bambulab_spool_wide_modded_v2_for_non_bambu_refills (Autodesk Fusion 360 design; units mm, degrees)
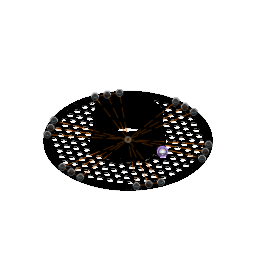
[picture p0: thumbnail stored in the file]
parameter "lattice_diameter" = 10.25
parameter "lattice_thickness" = 3.75
parameter "hole_diameter" = 3.5 comment "Hole Diameter of the rim"
base_mesh_feature "Base Mesh Feature"
convert_mesh "Convert Mesh" bodies "bambulab_spool_wide"
sketch "Sketch13" plane through (0, 0, -16.75) normal (0, 0, 1) x axis (-1, 0, 0)
  line L1 (92.6217, -5.7502) -> (99.4206, -5.9753)
  line L2 (92.483, -7.6633) -> (92.6217, -5.7502)
  line L3 (99.4206, -5.9753) -> (92.483, -7.6633)
  line L4 (0, 0) -> (-74.6153, -60.4003)
  line L5 (-89.6135, -34.4171) -> (0, 0)
  line L6 (-74.6153, -60.4003) -> (-89.6135, -34.4171)
  line L7 (-15.0006, -94.8162) -> (0, 0)
  line L8 (15.0006, -94.8189) -> (-15.0006, -94.8162)
  line L9 (0, 0) -> (15.0006, -94.8189)
  line L10 (0, 0) -> (74.6129, -60.399)
  line L11 (0, 0) -> (89.6159, -34.4185)
  line L12 (74.6129, -60.399) -> (89.6159, -34.4185)
  line L13 (89.6135, 34.4171) -> (0, 0)
  line L14 (74.6153, 60.4003) -> (89.6135, 34.4171)
  line L15 (0, 0) -> (74.6153, 60.4003)
  line L16 (0, 0) -> (-15.0006, 94.8189)
  line L17 (15.0006, 94.8162) -> (-15.0006, 94.8189)
  line L18 (0, 0) -> (15.0006, 94.8162)
  line L19 (0, 0) -> (-89.6159, 34.4185)
  line L20 (-89.6159, 34.4185) -> (-74.6129, 60.399)
  line L21 (0, 0) -> (-74.6129, 60.399)
  line L22 (0, 0) -> (-82.1144, 47.4088)
  line L23 (0, 0) -> (0, 94.8175)
  line L24 (0, 0) -> (82.1144, 47.4087)
  line L25 (0, 0) -> (82.1144, -47.4088)
  line L26 (0, 0) -> (0, -94.8175)
  line L27 (0, 0) -> (-82.1144, -47.4087)
  circle C1 centre (15.0006, -94.8189) radius 2
  circle C2 centre (-15.0006, -94.8162) radius 2
  circle C3 centre (89.6159, -34.4185) radius 2
  circle C4 centre (74.6153, 60.4003) radius 2
  circle C5 centre (-15.0006, 94.8189) radius 2
  circle C6 centre (-89.6159, 34.4185) radius 2
  circle C7 centre (-74.6153, -60.4003) radius 2
  circle C8 centre (74.6129, -60.399) radius 2
  circle C9 centre (89.6135, 34.4171) radius 2
  circle C10 centre (15.0006, 94.8162) radius 2
  circle C11 centre (-74.6129, 60.399) radius 2
  circle C12 centre (-89.6135, -34.4171) radius 2
  point P1 (0, 0)
  point P7 (0, 0)
  point P12 (-74.6153, -60.4003)
  point P18 (-74.6153, -60.4003)
  point P19 (0, 0)
  point P17 (-89.6135, -34.4171)
  point P20 (-89.6135, -34.4171)
  point P21 (-74.6153, -60.4003)
  point P22 (-82.1144, -47.4087)
  point P23 (0, 0)
  point P6 (-15.0006, -94.8162)
  point P24 (-15.0006, -94.8162)
  point P5 (15.0006, -94.8189)
  point P25 (15.0006, -94.8189)
  point P26 (0, 0)
  point P13 (74.6129, -60.399)
  point P27 (74.6129, -60.399)
  point P28 (0, 0)
  point P8 (89.6159, -34.4185)
  point P29 (89.6159, -34.4185)
  point P30 (0, 0)
  point P31 (89.6159, -34.4185)
  point P14 (89.6135, 34.4171)
  point P32 (89.6135, 34.4171)
  point P9 (74.6153, 60.4003)
  point P33 (74.6153, 60.4003)
  point P34 (0, 0)
  point P10 (-15.0006, 94.8189)
  point P35 (-15.0006, 94.8189)
  point P36 (0, 0)
  point P37 (-15.0006, 94.8189)
  point P15 (15.0006, 94.8162)
  point P38 (15.0006, 94.8162)
  point P39 (15.0006, 94.8162)
  point P40 (0, 0)
  point P11 (-89.6159, 34.4185)
  point P41 (-89.6159, 34.4185)
  point P42 (0, 0)
  point P16 (-74.6129, 60.399)
  point P43 (-74.6129, 60.399)
  point P44 (-89.6159, 34.4185)
  point P45 (0, -94.8175)
  point P46 (82.1144, -47.4088)
  point P47 (82.1144, 47.4087)
  point P48 (0, 94.8175)
  point P49 (-82.1144, 47.4088)
  point P50 (-82.1144, 47.4088)
  point P51 (0, 0)
  point P52 (0, 94.8175)
  point P53 (0, 0)
  point P54 (82.1144, 47.4087)
  point P55 (82.1144, -47.4088)
  point P56 (0, -94.8175)
  point P57 (-82.1144, -47.4087)
  point P58 (0, 0)
  coincident P1 P7
  coincident P12 P18
  coincident P7 P19
  coincident P17 P20
  coincident P12 P21
  midpoint L6 P22
  coincident P7 P23
  coincident P6 P24
  coincident P5 P25
  coincident P1 P26
  coincident P13 P27
  coincident P1 P28
  coincident P8 P29
  coincident P7 P30
  coincident P8 P31
  coincident P14 P32
  coincident P9 P33
  coincident P1 P34
  coincident P10 P35
  coincident P1 P36
  coincident P10 P37
  coincident P15 P38
  coincident P15 P39
  coincident P1 P40
  coincident P11 P41
  coincident P7 P42
  coincident P16 P43
  coincident P11 P44
  midpoint L8 P45
  midpoint L12 P46
  midpoint L14 P47
  midpoint L17 P48
  midpoint L20 P49
  coincident P49 P50
  coincident P1 P51
  coincident P48 P52
  coincident P7 P53
  coincident P47 P54
  coincident P46 P55
  coincident P45 P56
  coincident P22 P57
  coincident P1 P58
  dimension "d48" diameter C1 = 4
  dimension "d49" diameter C2 = 4
  dimension "d51" C-Pattern1-Angle = 360
  dimension "d53" C-Pattern2-Angle = 360
extrude "Extrude5" cut sketch "Sketch13" profile of C3 C4 C6 C7 C8 C9 C11 C12 against normal blind 25
sketch "Sketch14" plane through (0, 0, -17.85) normal (0, 0, 1) x axis (-1, 0, 0)
  line L1 (-23.297, 37.7968) -> (-24.4167, 37.0834)
  line L2 (-2.5625, 4.4384) -> (2.5625, 4.4384)
  line L3 (-5.125, 0) -> (-2.5625, 4.4384)
  line L4 (-2.5625, -4.4384) -> (-5.125, 0)
  line L5 (2.5625, -4.4384) -> (-2.5625, -4.4384)
  line L6 (5.125, 0) -> (2.5625, -4.4384)
  line L7 (2.5625, 4.4384) -> (5.125, 0)
  line L8 (5.125, -12.6268) -> (2.5625, -17.0651)
  line L9 (2.5625, -8.1884) -> (5.125, -12.6268)
  line L10 (-2.5625, -8.1884) -> (2.5625, -8.1884)
  line L11 (-5.125, -12.6268) -> (-2.5625, -8.1884)
  line L12 (-2.5625, -17.0651) -> (-5.125, -12.6268)
  line L13 (2.5625, -17.0651) -> (-2.5625, -17.0651)
  line L14 (0, -45.5) -> (0, 45.5)
  line L15 (-37, 0) -> (37, 0)
  line L16 (16.0601, -6.3134) -> (13.4976, -10.7518)
  line L17 (13.4976, -1.875) -> (16.0601, -6.3134)
  line L18 (8.3726, -1.875) -> (13.4976, -1.875)
  line L19 (5.8101, -6.3134) -> (8.3726, -1.875)
  line L20 (8.3726, -10.7518) -> (5.8101, -6.3134)
  line L21 (13.4976, -10.7518) -> (8.3726, -10.7518)
  line L22 (13.4976, 10.7518) -> (16.0601, 6.3134)
  line L23 (8.3726, 10.7518) -> (13.4976, 10.7518)
  line L24 (5.8101, 6.3134) -> (8.3726, 10.7518)
  line L25 (8.3726, 1.875) -> (5.8101, 6.3134)
  line L26 (13.4976, 1.875) -> (8.3726, 1.875)
  line L27 (16.0601, 6.3134) -> (13.4976, 1.875)
  line L28 (-5.125, -17.0651) -> (-5.125, 10.7518)
  line L29 (16.0601, -17.0651) -> (16.0601, 10.7518)
  line L30 (-5.125, 10.7518) -> (16.0601, 10.7518)
  line L31 (-5.125, -17.0651) -> (16.0601, -17.0651)
  line L32 (-92.4279, -85.5158) -> (-89.8654, -89.9542)
  line L33 (-89.8654, -89.9542) -> (-92.4279, -94.3926)
  line L34 (-92.4279, -94.3926) -> (-97.5529, -94.3926)
  line L35 (-97.5529, -94.3926) -> (-100.1154, -89.9542)
  line L36 (-100.1154, -89.9542) -> (-97.5529, -85.5158)
  line L37 (-97.5529, -85.5158) -> (-92.4279, -85.5158)
  line L38 (-92.4279, -98.1426) -> (-89.8654, -102.581)
  line L39 (-97.5529, -98.1426) -> (-92.4279, -98.1426)
  line L40 (-100.1154, -102.581) -> (-97.5529, -98.1426)
  line L41 (-97.5529, -107.0194) -> (-100.1154, -102.581)
  line L42 (-92.4279, -107.0194) -> (-97.5529, -107.0194)
  line L43 (-89.8654, -102.581) -> (-92.4279, -107.0194)
  line L44 (-100.8005, -96.2676) -> (-103.363, -100.706)
  line L45 (-103.363, -91.8292) -> (-100.8005, -96.2676)
  line L46 (-108.488, -91.8292) -> (-103.363, -91.8292)
  line L47 (-111.0505, -96.2676) -> (-108.488, -91.8292)
  line L48 (-108.488, -100.706) -> (-111.0505, -96.2676)
  line L49 (-103.363, -100.706) -> (-108.488, -100.706)
  line L50 (-108.488, -104.456) -> (-103.363, -104.456)
  line L51 (-103.363, -104.456) -> (-100.8005, -108.8944)
  line L52 (-100.8005, -108.8944) -> (-103.363, -113.3327)
  line L53 (-103.363, -113.3327) -> (-108.488, -113.3327)
  line L54 (-108.488, -113.3327) -> (-111.0505, -108.8944)
  line L55 (-111.0505, -108.8944) -> (-108.488, -104.456)
  line L56 (-71.2428, -85.5158) -> (-68.6803, -89.9542)
  line L57 (-68.6803, -89.9542) -> (-71.2428, -94.3926)
  line L58 (-71.2428, -94.3926) -> (-76.3678, -94.3926)
  line L59 (-76.3678, -94.3926) -> (-78.9303, -89.9542)
  line L60 (-78.9303, -89.9542) -> (-76.3678, -85.5158)
  line L61 (-76.3678, -85.5158) -> (-71.2428, -85.5158)
  line L62 (-71.2428, -98.1426) -> (-68.6803, -102.581)
  line L63 (-76.3678, -98.1426) -> (-71.2428, -98.1426)
  line L64 (-78.9303, -102.581) -> (-76.3678, -98.1426)
  line L65 (-76.3678, -107.0194) -> (-78.9303, -102.581)
  line L66 (-71.2428, -107.0194) -> (-76.3678, -107.0194)
  line L67 (-68.6803, -102.581) -> (-71.2428, -107.0194)
  line L68 (-79.6154, -96.2676) -> (-82.1779, -100.706)
  line L69 (-82.1779, -91.8292) -> (-79.6154, -96.2676)
  line L70 (-87.3029, -91.8292) -> (-82.1779, -91.8292)
  line L71 (-89.8654, -96.2676) -> (-87.3029, -91.8292)
  line L72 (-87.3029, -100.706) -> (-89.8654, -96.2676)
  line L73 (-82.1779, -100.706) -> (-87.3029, -100.706)
  line L74 (-87.3029, -104.456) -> (-82.1779, -104.456)
  line L75 (-82.1779, -104.456) -> (-79.6154, -108.8944)
  line L76 (-79.6154, -108.8944) -> (-82.1779, -113.3327)
  line L77 (-82.1779, -113.3327) -> (-87.3029, -113.3327)
  line L78 (-87.3029, -113.3327) -> (-89.8654, -108.8944)
  line L79 (-89.8654, -108.8944) -> (-87.3029, -104.456)
  line L80 (-50.0577, -85.5158) -> (-47.4952, -89.9542)
  line L81 (-47.4952, -89.9542) -> (-50.0577, -94.3926)
  line L82 (-50.0577, -94.3926) -> (-55.1827, -94.3926)
  line L83 (-55.1827, -94.3926) -> (-57.7452, -89.9542)
  line L84 (-57.7452, -89.9542) -> (-55.1827, -85.5158)
  line L85 (-55.1827, -85.5158) -> (-50.0577, -85.5158)
  line L86 (-50.0577, -98.1426) -> (-47.4952, -102.581)
  line L87 (-55.1827, -98.1426) -> (-50.0577, -98.1426)
  line L88 (-57.7452, -102.581) -> (-55.1827, -98.1426)
  line L89 (-55.1827, -107.0194) -> (-57.7452, -102.581)
  line L90 (-50.0577, -107.0194) -> (-55.1827, -107.0194)
  line L91 (-47.4952, -102.581) -> (-50.0577, -107.0194)
  line L92 (-58.4303, -96.2676) -> (-60.9928, -100.706)
  line L93 (-60.9928, -91.8292) -> (-58.4303, -96.2676)
  line L94 (-66.1178, -91.8292) -> (-60.9928, -91.8292)
  line L95 (-68.6803, -96.2676) -> (-66.1178, -91.8292)
  line L96 (-66.1178, -100.706) -> (-68.6803, -96.2676)
  line L97 (-60.9928, -100.706) -> (-66.1178, -100.706)
  line L98 (-66.1178, -104.456) -> (-60.9928, -104.456)
  line L99 (-60.9928, -104.456) -> (-58.4303, -108.8944)
  line L100 (-58.4303, -108.8944) -> (-60.9928, -113.3327)
  line L101 (-60.9928, -113.3327) -> (-66.1178, -113.3327)
  line L102 (-66.1178, -113.3327) -> (-68.6803, -108.8944)
  line L103 (-68.6803, -108.8944) -> (-66.1178, -104.456)
  line L104 (-28.8726, -85.5158) -> (-26.3101, -89.9542)
  line L105 (-26.3101, -89.9542) -> (-28.8726, -94.3926)
  line L106 (-28.8726, -94.3926) -> (-33.9976, -94.3926)
  line L107 (-33.9976, -94.3926) -> (-36.5601, -89.9542)
  line L108 (-36.5601, -89.9542) -> (-33.9976, -85.5158)
  line L109 (-33.9976, -85.5158) -> (-28.8726, -85.5158)
  line L110 (-28.8726, -98.1426) -> (-26.3101, -102.581)
  line L111 (-33.9976, -98.1426) -> (-28.8726, -98.1426)
  line L112 (-36.5601, -102.581) -> (-33.9976, -98.1426)
  line L113 (-33.9976, -107.0194) -> (-36.5601, -102.581)
  line L114 (-28.8726, -107.0194) -> (-33.9976, -107.0194)
  line L115 (-26.3101, -102.581) -> (-28.8726, -107.0194)
  line L116 (-37.2452, -96.2676) -> (-39.8077, -100.706)
  line L117 (-39.8077, -91.8292) -> (-37.2452, -96.2676)
  line L118 (-44.9327, -91.8292) -> (-39.8077, -91.8292)
  line L119 (-47.4952, -96.2676) -> (-44.9327, -91.8292)
  line L120 (-44.9327, -100.706) -> (-47.4952, -96.2676)
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  point P1 (0, 0)
  point P4 (0, 0)
  point P5 (0, 0)
  point P6 (0, 0)
  point P13 (0, 0)
  point P20 (0, -12.6268)
  point P9 (-5.125, 0)
  point P26 (16.0601, -6.3134)
  point P41 (16.0601, -17.0651)
  point P42 (-5.125, -17.0651)
  point P39 (-5.125, 10.7518)
  point P40 (16.0601, 10.7518)
  point P12 (5.125, 0)
  point P7 (2.5625, 4.4384)
  point P10 (-2.5625, -4.4384)
  point P15 (5.125, -12.6268)
  point P18 (-5.125, -12.6268)
  point P14 (2.5625, -17.0651)
  point P17 (-2.5625, -8.1884)
  point P29 (5.8101, -6.3134)
  point P32 (16.0601, 6.3134)
  point P35 (5.8101, 6.3134)
  coincident P1 P4
  coincident P1 P5
  coincident P1 P6
  coincident P5 P13
  vertical L14
  horizontal L15
  coincident P1 L14
  midpoint P4 L15
  midpoint P1 L14
  coincident P20 L14
  parallel L5 L15
  parallel L15 L21
  parallel L15 L26
  vertical L28
  vertical L29
  coincident P9 L28
  coincident P26 L29
  perpendicular L29 L30
  horizontal L31
  collinear L23 L30
  collinear L13 L31
  coincident L29 P41
  coincident L28 P42
  coincident P39 L30
  coincident L29 P40
  dimension "d56" diameter = 183.4
  dimension "d57" diameter = 89
  dimension "d62" diameter = 179.65 (= "183.4 mm - lattice_thickness")
  dimension "d63" distance P9 P12 = 10.25 (= "lattice_diameter")
  dimension "d64" distance P7 P10 = 10.25 (= "lattice_diameter")
  dimension "d65" distance P15 P18 = 10.25 (= "lattice_diameter")
  dimension "d66" distance P14 P17 = 10.25 (= "lattice_diameter")
  dimension "d67" distance L5 L10 = 3.75 (= "lattice_thickness")
  dimension "d68" distance P26 P29 = 10.25 (= "lattice_diameter")
  dimension "d69" distance L6 L19 = 3.75 (= "lattice_thickness")
  dimension "d70" distance L9 L20 = 3.75 (= "lattice_thickness")
  dimension "d71" distance P32 P35 = 10.25 (= "lattice_diameter")
  dimension "d72" distance L18 L26 = 3.75 (= "lattice_thickness")
  dimension "d73" distance L7 L25 = 3.75 (= "lattice_thickness")
  dimension "d74" distance P41 P42 = 21.1851
  dimension "d75" distance P40 P41 = 27.8169
  dimension "d78" R-Pattern1-uDistance = 21.1851
  dimension "d79" R-Pattern1-vDistance = 24.0669 (= "27.816899 mm - lattice_thickness")
extrude "Extrude6" cut sketch "Sketch14" distance 30
work_plane "WorkPlane3" RotateAngle 45
sketch "Sketch16" plane through (27.1973, 30.4798, 1.2) normal (0.7071, 0.7071, -0.0003) x axis (-0.0041, 0.0036, -1)
  line L1 (17.7883, -26.5886) -> (17.7779, -28.5173)
  circle C1 centre (17.5808, -27.9755) radius 1.1
  point P2 (17.5808, -27.9755)
  dimension "d84" diameter C1 = 2.2
  dimension "d85" distance P2 L1 = 0.2
extrude "Extrude7" cut sketch "Sketch16" profile of C1 against normal blind 13
work_plane "WorkPlane4" RotateAngle 120
sketch "Sketch17" plane through (37.7529, -15.5941, 1.2) normal (0.6096, -0.7926, -0.0143) x axis (0.0109, 0.0265, -0.9996)
  line L1 (19.3005, 6.8332) -> (19.2658, 5.9127)
  circle C1 centre (17.9921, 7.9641) radius 1.1
  point P2 (17.9921, 7.9641)
  dimension "d89" diameter C1 = 2.2
  dimension "d93" distance P2 L1 = 1.35
extrude "Extrude8" cut sketch "Sketch17" profile of C1 against normal blind 10.5
sketch "Sketch18" plane through (0, 0, -17.85) normal (0, 0, 1) x axis (-1, 0, 0)
  line L1 (-48.5558, 4.4764) -> (-47.9524, 5.5214)
  line L2 (-40.6099, 4.4226) -> (-48.5558, 4.4764)
  line L3 (-40.4572, 5.6509) -> (-40.6099, 4.4226)
  line L4 (-47.9524, 5.5214) -> (-40.4572, 5.6509)
  line L5 (-44, 2.7549) -> (-40.755, 2.7549)
  line L6 (-44, -2.9962) -> (-44, 2.7549)
  line L7 (-40.738, -2.9962) -> (-44, -2.9962)
  circle C1 centre (0, 0) radius 40.848
  point P1 (0, 0)
  point P6 (0, 0)
  point P7 (-40.755, 2.7549)
  point P10 (-40.738, -2.9962)
  coincident P1 P6
  coincident C1 P7
  horizontal L5
  perpendicular L5 L6
  coincident C1 P10
  perpendicular L6 L7
  dimension "d94" diameter C1 = 81.696
extrude "Extrude9" cut sketch "Sketch18" profile of C1 L5 L6 L7 along normal blind 9
sketch "Sketch19" plane through (7.5003, 47.4081, -16.75) normal (-0.6984, 0.1105, 0.7071) x axis (0.1563, 0.9877, 0)
  circle C1 centre (48, 0) radius 1.75
  dimension "d101" diameter C1 = 3.5 (= "hole_diameter")
extrude "Extrude11" add sketch "Sketch13" profile of C1 C2 C5 C10 against normal blind 3.6
work_plane "WorkPlane8" RotateAngle 45
sketch "Sketch20" plane through (44.8068, 17.2086, -16.75) normal (0.2535, -0.6601, 0.7071) x axis (0.9335, 0.3585, 0)
  circle C1 centre (48, 0) radius 1.75
  dimension "d107" diameter C1 = 3.5 (= "hole_diameter")
extrude "Extrude12" new body sketch "Sketch20" distance 20
work_plane "WorkPlane9" RotateAngle 45
sketch "Sketch22" plane through (37.3076, 30.2002, -16.75) normal (-0.4449, 0.5496, 0.7071) x axis (-0.7773, -0.6292, 0)
  circle C1 centre (-48, 0) radius 1.75
  dimension "d111" diameter C1 = 3.5 (= "hole_diameter")
extrude "Extrude13" new body sketch "Sketch22" distance 20
circular_pattern "C-Pattern1" TotalAngle 360
combine "Combine1"
sketch "Sketch25" plane through (0, 0, -17.85) normal (0, 0, 1) x axis (-1, 0, 0)
  line L1 (-40.6099, -4.4226) -> (-44.284, -4.3789)
  line L2 (-40.7252, -3.1909) -> (-40.6099, -4.4226)
  line L3 (-44.3822, -3.2357) -> (-40.7252, -3.1909)
  line L4 (-40.771, 2.5396) -> (-40.6723, 3.8064)
  line L5 (-40.8302, 1.2704) -> (-40.771, 2.5396)
  line L6 (-40.85, 0) -> (-40.8302, 1.2704)
  line L7 (-40.8302, -1.2704) -> (-40.85, 0)
  line L8 (-40.771, -2.5396) -> (-40.8302, -1.2704)
  line L9 (-44.1, 2.7) -> (-40.6723, 3.8064)
  line L10 (-43.9, -3.1) -> (-44.1, 2.7)
  line L11 (-40.771, -2.5396) -> (-43.9, -3.1)
  arc A1 centre (0, 0) radius 44.5 clockwise from (-44.284, -4.3789) to (-44.3822, -3.2357)
  point P7 (-40.6723, 3.8064)
  point P13 (-40.6723, 3.8064)
  point P12 (-40.771, -2.5396)
  point P16 (-40.771, -2.5396)
  coincident P7 P13
  coincident P12 P16
extrude "Extrude14" cut sketch "Sketch25" profile of L4 L5 L6 L7 L8 L9 L10 L11 no distance stored
named bodies: "bambulab_spool_wide"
